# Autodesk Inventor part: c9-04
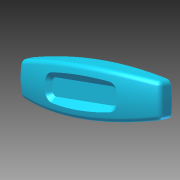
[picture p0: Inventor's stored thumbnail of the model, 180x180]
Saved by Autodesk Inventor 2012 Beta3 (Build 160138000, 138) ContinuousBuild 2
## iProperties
Created: 2010-12
Part Number: c9-04
Material: Default
Document SubType Name: Modeling
Designer: Beta-8540w
Density: 1 g/cm^3
Author: Beta-8540w
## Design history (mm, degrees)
sketch "Sketch1"
  geometry: L1 (-60, -12)-(60, -12); L2 (60, -12)-(60, 12); L3 (60, 12)-(-60, 12); L4 (-60, 12)-(-60, -12); A1 r 350 centre (0, -332.819) between (60, 12) and (-60, 12); A2 r 350 centre (0, 332.819) between (-60, -12) and (60, -12); 3 further points
  constraints: 8 end point, 4 point on circle, 2 centre point, 2 midpoint, 2 parallel, 1 equal radius, 1 horizontal, 1 horizontal alignment, 1 perpendicular, 1 vertical alignment
  dimensions: "d0" = 120 distance of L3.end L2.end; "d1" = 24 distance of L2.end L1.end; "d2" = 350 radius of A1
workplane "Work Plane4"
sketch "Sketch5"
  geometry: L1 (-60, 12)-(-60, -12) reference; L2 (60, -12)-(60, 12) reference; L3 (-58, 10.314)-(-58, -10.314); L4 (58, -10.314)-(58, 10.314); A1 r 350 centre (0, 332.819) between (-60, -12) and (60, -12) reference; A2 r 350 centre (0, -332.819) between (60, 12) and (-60, 12) reference; A3 r 348 centre (0, 332.819) between (-58, -10.314) and (58, -10.314); A4 r 348 centre (0, -332.819) between (58, 10.314) and (-58, 10.314); 1 further point
  constraints: 4 end point, 4 point on circle, 2 centre point, 3 other
  dimensions: "d37" = 2 distance between parallel lines of L2 L4
sketch "Sketch6"
  geometry: L1 (-60, 0)-(60, 0); L2 (60, 0)-(58.843, 22.085); L3 (-60, 0)-(-58.779, 23.307); A1 r 691.758 centre (630.81, -36.204) between (-60, 0) and (-58, -100); A2 r 691.758 centre (-630.81, -36.204) between (58, -100) and (60, 0); 1 further point
  constraints: 6 end point, 4 point on circle, 2 centre point, 2 tangent, 1 horizontal
  dimensions: "d53" = 87 deg angle of L1 L3; "d54" = 87 deg angle of L1 L2 (= d53)
sketch "Sketch7"
  geometry: L1 (17.181, 0)-(12, 0) reference; L2 (15.181, -100)-(10.314, -100) reference; L3 (17.181, 0)-(16.768, 11.838); A1 r 911.322 centre (-893.585, -31.805) between (15.181, -100) and (17.181, 0); 1 further point
  constraints: 2 end point, 2 point on circle, 1 centre point, 1 tangent
  dimensions: "d56" = 88 deg angle of L1 L3
feature "LoftSrf2" sketch "Sketch5", "Sketch6", "Sketch7" dims "d57" = 0, "d58" = 90 deg, "d59" = 0, "d60" = 90 deg, "d61" = 0, "d62" = 90 deg, "d63" = 0, "d64" = 90 deg, "d65" = 0, "d66" = 90 deg
sketch "Sketch2"
  geometry: L1 (-75, -16)-(75, -16); L2 (-75, -60)-(75, -60); A1 r 183.781 centre (0, -183.781) between (75, -16) and (-75, -16); 2 further points
  constraints: 4 end point, 3 point on circle, 1 centre point, 1 coincident, 1 horizontal, 1 parallel
  dimensions: "d5" = 16 distance from line of point (0, 0) L1; "d7" = 60 distance from line of point (0, 0) L2; "d55" = 150 distance of L1.start L1.end
feature "RevolutionSrf1" sketch "Sketch2" dims angle "d8" = 40 deg
patch "Boundary Patch1" dims "d13" = 0, "d67" = 0, "d68" = 0, "d69" = 0, "d70" = 0
workplane "Work Plane1"
sketch "Sketch3"
  geometry: L1 (52, -85)-(52, -73); L2 (38, -73)-(38, -85); A1 r 7 centre (45, -73) between (52, -73) and (38, -73); A2 r 7 centre (45, -85) between (38, -85) and (52, -85); 1 further point
  constraints: 4 end point, 4 point on circle, 4 tangent, 2 centre point, 1 parallel, 1 vertical
  dimensions: "d15" = 12 distance of L1.start L1.end; "d16" = 7 radius of A1; "d50" = 45 horizontal distance of A1.centre point (0, 0); "d51" = 85 vertical distance of point (0, 0) A2.centre
extrude_surface "ExtrusionSrf2" sketch "Sketch3" dims "d19" = 14, "d20" = 5 deg
pattern_linear "Rectangular Pattern1" dims "d23" = 90
workplane "Work Plane2"
feature "Sculpt1"
sketch "Sketch4"
  geometry: L1 (-24.5, 6)-(24.5, 6); L2 (27.5, 3)-(27.5, -3); L3 (24.5, -6)-(-24.5, -6); L4 (-27.5, -3)-(-27.5, 3); A1 r 3 centre (-24.5, 3) between (-24.5, 6) and (-27.5, 3); A2 r 3 centre (24.5, 3) between (27.5, 3) and (24.5, 6); A3 r 3 centre (24.5, -3) between (24.5, -6) and (27.5, -3); A4 r 3 centre (-24.5, -3) between (-27.5, -3) and (-24.5, -6); 6 further points
  constraints: 8 end point, 8 point on circle, 8 tangent, 6 point on line, 4 centre point, 3 equal radius, 2 midpoint, 2 parallel, 1 horizontal, 1 horizontal alignment, 1 perpendicular, 1 vertical alignment
  dimensions: "d28" = 55 distance of point (27.5, -6) point (-27.5, -6); "d29" = 12 distance of point (27.5, 6) point (27.5, -6); "d30" = 3 radius of A1
extrude_surface "ExtrusionSrf6" sketch "Sketch4" dims "d31" = 14, "d32" = 45 deg
patch "Boundary Patch2" dims "d33" = 0, "d34" = 0
fillet "Fillet1" dims "d79" = 4, "d80" = 3, "d81" = 1
feature "Sculpt2"
node "Splitting Plane 1"
shell "Shell1" dims "d83" = 2
split "Split1"
  body "Solid1"
body "Srf2"
body "Srf3"
body "Srf4"
body "Srf5"
body "Srf6"
body "Srf7"
body "Srf8"
body "Srf9"
body "Srf11"
feature "Stitch Surface1"
body "Srf12"
extrude_surface "ExtrusionSrf3"
extrude_surface "ExtrusionSrf4"
extrude_surface "ExtrusionSrf5"
node "Front"
node "Back"
other parameters: "d14" = -24, "d52" = -6
